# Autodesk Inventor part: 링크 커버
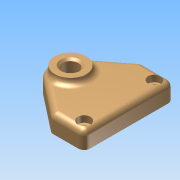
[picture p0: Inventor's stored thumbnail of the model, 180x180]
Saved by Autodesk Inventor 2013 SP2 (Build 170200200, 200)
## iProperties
Created: 2025-07
Part Number: 링크 커버
Material: Generic
Document SubType Name: Modeling
Designer: a
Density: 1 g/cm^3
Author: a
변환 표준: STEP AP214IS
전처리기: Build: 200, Release: 2013 SP2 Update 6 - Date: Thu 07/17/2014
전송 단위: 밀리미터
불확실성: 0.01
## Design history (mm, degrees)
node "링크 커버1"
node "솔리드1"
node "기준1"
